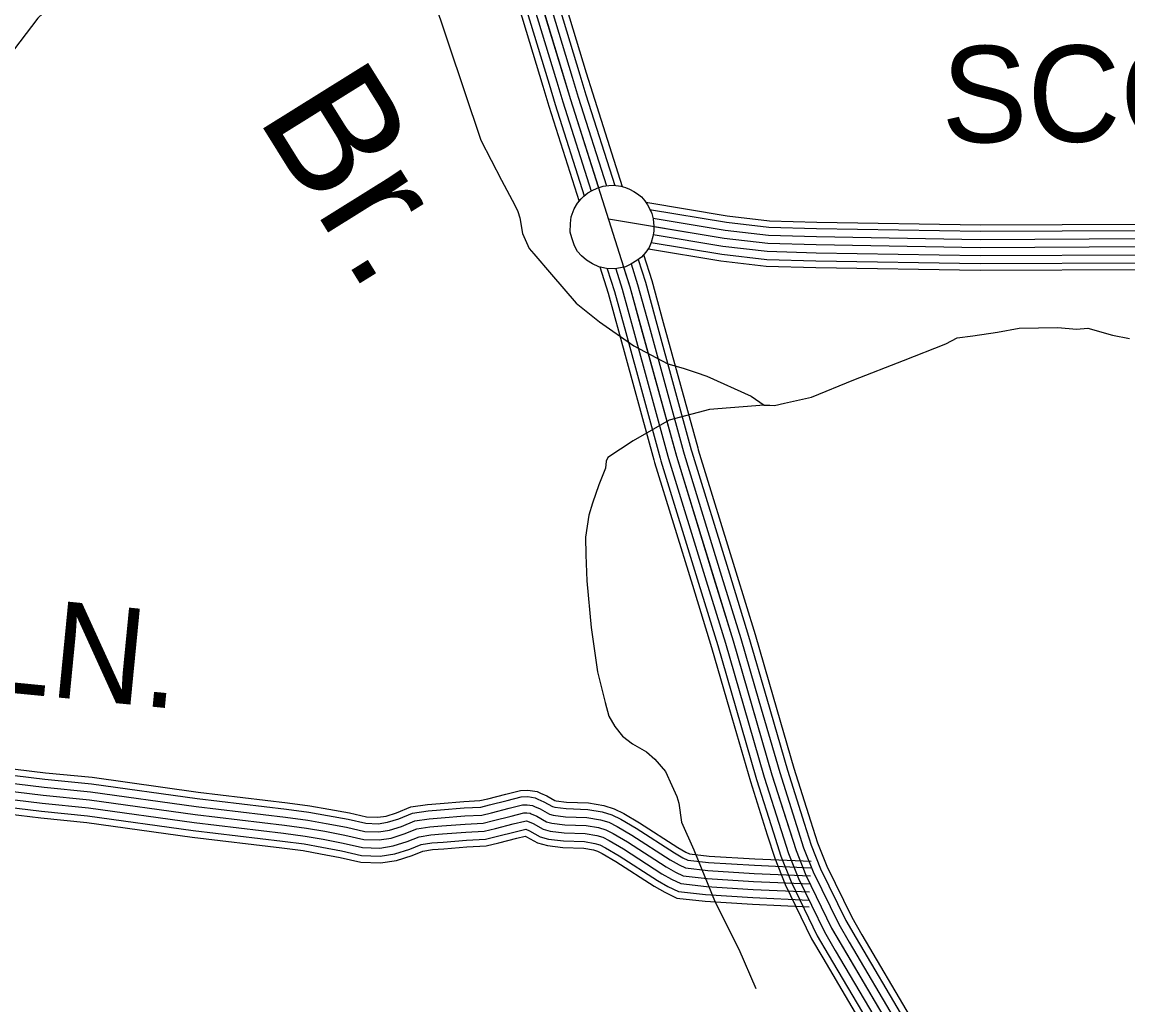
# Model space of a CAD drawing. Extents: x 1551132 to 1791609, y 378168 to 563823.
# Drawn here: x 1653929 to 1658175, y 416489 to 420262 of the extents above; entities that cross this region are included whole.
import ezdxf

# ---------------------------------------------------------------- set-up
doc = ezdxf.new("R2010")
doc.units = 0
for name, color, linetype in [('DESIGN - DRAINAGE - Bridges and Cross Drains Size Text', 7, 'Continuous'), ('DESIGN - ROW - Right-of-Way and Easement Labels', 7, 'Continuous'), ('DESIGN - TRANSPORTATION - Text', 7, 'Continuous'), ('SURVEY - CENTERLINE - Preliminary Text', 7, 'Continuous'), ('SURVEY - CONTOURS - Index with Text', 7, 'Continuous'), ('SURVEY - TRANSPORTATION - Roads', 7, 'Continuous'), ('SURVEY - VEGETATION - Features with Text', 7, 'Continuous')]:
    doc.layers.add(name, color=color, linetype=linetype)

msp = doc.modelspace()

# ---------------------------------------------------------------- linework, layer by layer
at = {"layer": 'DESIGN - TRANSPORTATION - Text'}
for points in [[(1655370.239, 420674.916), (1655323.215, 420654.533), (1655299.141, 420642.682), (1655271, 420620.848), (1655208.709, 420577.222), (1655168.635, 420565.48), (1655134.561, 420553.705), (1655086.529, 420548.038), (1655014.397, 420528.512), (1654904.366, 420523.287), (1654828.36, 420521.82), (1654722.362, 420520.57), (1654632.323, 420515.195), (1654514.267, 420506.02), (1654426.236, 420500.636), (1654370.187, 420493.019), (1654326.047, 420471.294), (1654255.965, 420457.768), (1654215.833, 420438.018), (1654159.659, 420410.375), (1654103.452, 420378.716), (1654051.17, 420335.015), (1653988.788, 420277.364), (1653851.608, 420096.042)], [(1655500.719, 420374.917), (1655690.564, 419808.285), (1655769.562, 419655.473), (1655820.928, 419558.954), (1655832.769, 419534.828), (1655840.611, 419510.736), (1655850.21, 419450.568), (1655875.835, 419392.291), (1655893.701, 419372.132), (1655961.183, 419293.53), (1656056.455, 419182.678), (1656145.987, 419111.926), (1656277.375, 419018.848), (1656408.914, 418949.805), (1656466.804, 418933.363), (1656516.695, 418916.988), (1656558.602, 418902.662), (1656728.09, 418825.335), (1656777.863, 418790.934), (1656799.863, 418790.776), (1656817.862, 418790.651), (1656855.912, 418798.393), (1656960.059, 418821.694), (1657122.489, 418888.654), (1657312.976, 418963.422), (1657475.38, 419026.374), (1657519.529, 419050.1), (1657579.578, 419057.692), (1657673.668, 419071.042), (1657757.766, 419086.476), (1657905.779, 419089.434), (1657977.735, 419082.909), (1658021.751, 419086.609), (1658115.574, 419059.9), (1658181.489, 419047.408)], [(1656777.863, 418790.934), (1656567.927, 418775.317), (1656413.064, 418734.008), (1656275.408, 418654.831), (1656177.952, 418590.929), (1656171.861, 418576.945), (1656169.677, 418548.919), (1656143.253, 418485.001), (1656118.795, 418415.057), (1656104.496, 418369.081), (1656091.946, 418285.037), (1656093.504, 418216.911), (1656096.846, 418116.725), (1656113.678, 417938.32), (1656138.561, 417767.865), (1656167.785, 417649.462), (1656181.443, 417597.286), (1656205.176, 417557.052), (1656234.942, 417520.784), (1656272.741, 417490.467), (1656326.54, 417460.032), (1656358.347, 417431.765), (1656400.046, 417385.389), (1656423.688, 417331.137), (1656443.412, 417288.928), (1656451.245, 417262.827), (1656460.77, 417190.642), (1656508.069, 417084.139), (1656590.75, 416883.226), (1656681.564, 416702.288), (1656746.571, 416551.584)]]:
    msp.add_lwpolyline(points, dxfattribs=at)
at = {"layer": 'SURVEY - CENTERLINE - Preliminary Text'}
for points in [[(1655852.144, 420567.031), (1656034.773, 419964.59), (1656262.767, 419245.613), (1656441.104, 418595.096), (1656659.149, 417886.202), (1656808.27, 417372.164), (1656900.643, 417080.964), (1656938.134, 416986.529), (1657037.056, 416783.482), (1657263.076, 416399.263), (1657481.045, 416009.087), (1657530.436, 415896.542), (1657577.685, 415759.955), (1657642.625, 415569.133), (1657699.398, 415352.311), (1657761.688, 415053.27), (1657882.535, 414501.314), (1658040.423, 413782.77)], [(1655896.06, 420529.03), (1656041.115, 420050.517)], [(1655925.726, 420538.021), (1656070.781, 420059.509)], [(1655950.334, 420545.488), (1656095.388, 420066.976)], [(1655783.413, 420494.879), (1655928.467, 420016.366)], [(1655807.062, 420502.054), (1655952.117, 420023.541)], [(1655836.728, 420511.046), (1655981.783, 420032.533)], [(1655866.394, 420520.038), (1656011.449, 420041.525)], [(1656070.781, 420059.526), (1656093.988, 419982.957), (1656204.577, 419634.223)], [(1656095.388, 420066.984), (1656118.554, 419990.574), (1656232.66, 419630.748)], [(1655928.459, 420016.383), (1655951.95, 419938.906), (1656067.689, 419573.921)], [(1655952.117, 420023.558), (1655975.558, 419946.223), (1656087.022, 419594.713)], [(1655981.783, 420032.55), (1656005.165, 419955.406), (1656113.596, 419613.472)], [(1656011.449, 420041.542), (1656034.773, 419964.59), (1656142.004, 419626.431)], [(1656041.115, 420050.534), (1656064.381, 419973.773), (1656172.27, 419633.548)], [(1656267.409, 419333.515), (1656292.5, 419254.396), (1656336.382, 419094.367)], [(1656294.458, 419350.774), (1656322.233, 419263.188), (1656366.273, 419102.559)], [(1656315.541, 419369.383), (1656346.899, 419270.48), (1656391.073, 419109.359)], [(1656147.337, 419322.748), (1656179.594, 419221.029), (1656222.851, 419063.233)], [(1656175.761, 419314.873), (1656203.302, 419228.037), (1656246.693, 419069.775)], [(1656208.244, 419314.998), (1656233.035, 419236.829), (1656276.584, 419077.967)], [(1656238.776, 419321.265), (1656262.767, 419245.613), (1656306.483, 419086.167)], [(1656276.575, 419077.983), (1656408.772, 418595.762)], [(1656306.475, 419086.184), (1656438.671, 418603.963)], [(1656336.374, 419094.384), (1656468.57, 418612.163)], [(1656366.265, 419102.576), (1656498.461, 418620.355)], [(1656391.064, 419109.376), (1656523.261, 418627.155)], [(1656222.843, 419063.258), (1656355.04, 418581.037)], [(1656246.684, 419069.791), (1656378.881, 418587.57)], [(1656468.57, 418612.171), (1656470.879, 418603.746), (1656615.025, 418135.1)], [(1656498.47, 418620.363), (1656500.645, 418612.405), (1656644.649, 418144.209)], [(1656523.269, 418627.155), (1656525.344, 418619.58), (1656669.232, 418151.776)], [(1656355.04, 418581.07), (1656357.823, 418570.887), (1656502.511, 418100.491)], [(1656378.873, 418587.595), (1656381.564, 418577.787), (1656526.136, 418107.758)], [(1656408.772, 418595.787), (1656411.33, 418586.445), (1656555.76, 418116.867)], [(1656438.671, 418603.979), (1656441.104, 418595.096), (1656585.393, 418125.983)], [(1656644.649, 418144.226), (1656718.556, 417903.953), (1656788.096, 417664.213)], [(1656669.232, 418151.792), (1656743.197, 417911.32), (1656812.795, 417671.38)], [(1656526.136, 418107.775), (1656599.742, 417868.452), (1656669.015, 417629.662)], [(1656555.76, 418116.883), (1656629.45, 417877.327), (1656698.781, 417638.304)], [(1656585.393, 418126), (1656659.149, 417886.202), (1656728.556, 417646.938)], [(1656615.025, 418135.117), (1656688.848, 417895.077), (1656758.33, 417655.571)], [(1656502.511, 418100.508), (1656576.059, 417861.376), (1656645.274, 417622.779)], [(1656698.781, 417638.321), (1656778.604, 417363.155), (1656843.394, 417158.908)], [(1656728.556, 417646.954), (1656808.27, 417372.164), (1656872.944, 417168.283)], [(1656758.33, 417655.588), (1656837.936, 417381.172), (1656902.493, 417177.659)], [(1656788.096, 417664.23), (1656867.602, 417390.181), (1656932.042, 417187.034)], [(1656812.795, 417671.397), (1656892.21, 417397.648), (1656956.55, 417194.809)], [(1656645.274, 417622.795), (1656725.289, 417346.971), (1656790.287, 417142.058)], [(1656669.015, 417629.679), (1656748.938, 417354.147), (1656813.845, 417149.533)], [(1656872.935, 417168.3), (1656900.643, 417080.964), (1656938.134, 416986.529), (1657037.056, 416783.482), (1657078.08, 416713.738)], [(1656902.485, 417177.675), (1656929.859, 417091.381), (1656966.516, 416999.054), (1657064.389, 416798.149), (1657104.796, 416729.455)], [(1656932.034, 417187.051), (1656959.075, 417101.807), (1656994.891, 417011.579), (1657091.73, 416812.824), (1657131.521, 416745.172)], [(1656956.542, 417194.826), (1656983.316, 417110.449), (1657018.44, 417021.971), (1657114.404, 416824.991), (1657153.687, 416758.214)], [(1656790.279, 417142.074), (1656818.92, 417051.814), (1656858.744, 416951.486), (1656960.591, 416742.447), (1657003.34, 416669.77)], [(1656813.837, 417149.55), (1656842.211, 417060.122), (1656881.377, 416961.478), (1656982.382, 416754.139), (1657024.64, 416682.304)], [(1656843.386, 417158.925), (1656871.427, 417070.548), (1656909.751, 416974.003), (1657009.724, 416768.815), (1657051.364, 416698.021)], [(1657131.512, 416745.197), (1657316.866, 416430.106), (1657383.106, 416311.528)], [(1657153.67, 416758.231), (1657339.174, 416442.898), (1657405.556, 416324.07)], [(1657078.072, 416713.755), (1657263.076, 416399.263), (1657328.982, 416281.285)], [(1657104.788, 416729.472), (1657289.967, 416414.689), (1657356.048, 416296.402)], [(1657003.332, 416669.787), (1657187.844, 416356.129), (1657253.284, 416238.993)], [(1657024.631, 416682.312), (1657209.285, 416368.421), (1657274.859, 416251.043)], [(1657051.356, 416698.038), (1657236.185, 416383.838), (1657301.916, 416266.168)]]:
    msp.add_lwpolyline(points, dxfattribs=at)
at = {"layer": 'SURVEY - CONTOURS - Index with Text'}
for points in [[(1653598.962, 417431.064), (1654019.369, 417379.912), (1654198.023, 417362.454), (1654604.405, 417305.152), (1654947.447, 417264.552), (1655033.928, 417253.56), (1655106.352, 417240.559), (1655186.308, 417225.551), (1655251.807, 417210.45), (1655295.072, 417208.934), (1655326.505, 417213.875), (1655367.112, 417226.567), (1655421.569, 417248.893), (1655485.201, 417258.327), (1655533.7, 417262.285), (1655625.04, 417269.71), (1655686.255, 417272.852), (1655717.854, 417280.502), (1655785.952, 417297.995), (1655842.101, 417311.603), (1655871.334, 417313.37), (1655906.1, 417308.02), (1655919.833, 417301.145), (1655943.574, 417290.878), (1655974.998, 417273.119), (1655979.498, 417271.911), (1656019.572, 417266.794), (1656103.537, 417264.094), (1656162.335, 417253.819), (1656202.726, 417241.927), (1656239.95, 417222.935), (1656299.532, 417188.234), (1656446.387, 417093.273), (1656477.353, 417075.739), (1656491.502, 417068.997), (1656566.759, 417060.222), (1656742.505, 417049.455), (1656958.133, 417039.955)], [(1652785.914, 417349.136), (1652920.786, 417384.145), (1652980.91, 417403.713), (1653025.375, 417407.096), (1653070.899, 417405.029), (1653194.797, 417394.062), (1653588.362, 417344.995), (1654009.911, 417293.702), (1654187.748, 417276.326), (1654593.255, 417219.15), (1654936.889, 417178.474), (1655020.795, 417167.816), (1655090.694, 417155.265), (1655168.567, 417140.648), (1655240.44, 417124.081), (1655300.33, 417121.973), (1655346.288, 417129.198), (1655396.553, 417144.915)], [(1653595.945, 417406.53), (1654016.669, 417355.337), (1654195.09, 417337.903), (1654601.23, 417280.643), (1654944.439, 417240.018), (1655030.187, 417229.126), (1655101.893, 417216.25), (1655181.25, 417201.35), (1655248.565, 417185.833), (1655296.572, 417184.141), (1655332.146, 417189.742), (1655375.504, 417203.292), (1655428.169, 417224.884), (1655488.018, 417233.751), (1655535.708, 417237.643), (1655626.673, 417245.051), (1655689.821, 417248.285), (1655723.837, 417256.518), (1655791.936, 417274.019), (1655845.784, 417287.069), (1655870.184, 417288.536), (1655898.5, 417284.186), (1655909.383, 417278.736), (1655932.557, 417268.711), (1655965.573, 417250.052), (1655974.715, 417247.61), (1656017.605, 417242.127), (1656101.003, 417239.443), (1656156.694, 417229.71), (1656193.543, 417218.868), (1656228.109, 417201.226), (1656286.599, 417167.166), (1656433.57, 417072.122), (1656465.928, 417053.805), (1656484.569, 417044.922), (1656564.576, 417035.596), (1656741.205, 417024.771), (1656957.042, 417015.263)], [(1653588.362, 417344.995), (1654009.911, 417293.702), (1654187.748, 417276.326), (1654593.255, 417219.15), (1654936.889, 417178.474), (1655020.795, 417167.816), (1655090.694, 417155.265), (1655168.567, 417140.648), (1655240.44, 417124.081), (1655300.33, 417121.973), (1655346.288, 417129.198), (1655396.553, 417144.915), (1655444.71, 417164.658), (1655495.093, 417172.124), (1655540.741, 417175.85), (1655630.773, 417183.175), (1655698.779, 417186.658), (1655738.845, 417196.359), (1655806.952, 417213.859), (1655855.026, 417225.509), (1655867.309, 417226.251), (1655879.442, 417224.384), (1655883.167, 417222.518), (1655904.925, 417213.109), (1655941.94, 417192.192), (1655962.723, 417186.633), (1656012.672, 417180.25), (1656094.637, 417177.617), (1656142.561, 417169.241), (1656170.502, 417161.016), (1656198.393, 417146.783), (1656254.15, 417114.315), (1656401.438, 417019.071), (1656437.287, 416998.77), (1656467.178, 416984.528), (1656559.084, 416973.811), (1656737.947, 416962.853), (1656954.317, 416953.319)], [(1653592.154, 417375.762), (1654013.294, 417324.519), (1654191.423, 417307.119), (1654597.239, 417249.893), (1654940.664, 417209.242), (1655025.487, 417198.467), (1655096.294, 417185.758), (1655174.908, 417170.999), (1655244.507, 417154.957), (1655298.455, 417153.057), (1655339.213, 417159.466), (1655386.028, 417174.108), (1655436.436, 417194.775), (1655491.559, 417202.942), (1655538.225, 417206.75), (1655628.723, 417214.109), (1655694.305, 417217.467), (1655731.337, 417226.434), (1655799.444, 417243.935), (1655850.401, 417256.285), (1655868.75, 417257.394), (1655888.975, 417254.285), (1655896.275, 417250.627), (1655918.741, 417240.91), (1655953.757, 417221.118), (1655968.723, 417217.118), (1656015.139, 417211.184), (1656097.82, 417208.534), (1656149.627, 417199.476), (1656182.026, 417189.942), (1656213.251, 417174.008), (1656270.374, 417140.741), (1656417.504, 417045.597), (1656451.612, 417026.288), (1656475.869, 417014.729), (1656561.826, 417004.704), (1656739.58, 416993.812), (1656955.683, 416984.287)], [(1653584.571, 417314.227), (1654006.527, 417262.884), (1654184.073, 417245.534), (1654589.272, 417188.408), (1654933.114, 417147.707), (1655016.104, 417137.165), (1655085.094, 417124.773), (1655162.225, 417110.298), (1655236.374, 417093.206), (1655302.205, 417090.889), (1655353.362, 417098.931), (1655407.078, 417115.723), (1655452.985, 417134.54), (1655498.626, 417141.307), (1655543.258, 417144.949), (1655632.823, 417152.241), (1655703.254, 417155.849), (1655746.353, 417166.283), (1655814.46, 417183.783), (1655859.651, 417194.734), (1655865.867, 417195.109), (1655869.909, 417194.484), (1655870.059, 417194.409), (1655891.108, 417185.308), (1655930.124, 417163.266), (1655956.723, 417156.149), (1656010.205, 417149.316), (1656091.454, 417146.699), (1656135.494, 417139.007), (1656158.977, 417132.09), (1656183.535, 417119.557), (1656237.925, 417087.889), (1656385.372, 416992.545), (1656422.962, 416971.253), (1656458.487, 416954.328), (1656556.343, 416942.919), (1656736.313, 416931.894), (1656952.95, 416922.352)], [(1653577.637, 417257.934), (1654000.344, 417206.5), (1654177.357, 417189.208), (1654581.972, 417132.156), (1654926.206, 417091.405), (1655007.512, 417081.08), (1655074.852, 417068.988), (1655150.617, 417054.763), (1655228.94, 417036.712), (1655305.647, 417034.012), (1655366.295, 417043.546), (1655426.327, 417062.322), (1655468.118, 417079.447), (1655505.101, 417084.931), (1655547.866, 417088.422), (1655636.573, 417095.639), (1655711.454, 417099.473), (1655760.078, 417111.248), (1655828.193, 417128.748), (1655860.759, 417136.64), (1655865.834, 417134.449), (1655908.499, 417110.331), (1655945.757, 417100.373), (1656005.689, 417092.706), (1656085.637, 417090.139), (1656122.561, 417083.689), (1656137.902, 417079.172), (1656156.36, 417069.755), (1656208.242, 417039.538), (1656355.972, 416944.011), (1656396.763, 416920.91), (1656442.579, 416899.084), (1656551.318, 416886.401), (1656733.33, 416875.251), (1656950.458, 416865.684)], [(1653580.779, 417283.46), (1654003.152, 417232.067), (1654180.407, 417214.75), (1654585.28, 417157.657), (1654929.339, 417116.931), (1655011.404, 417106.506), (1655079.494, 417094.281), (1655155.884, 417079.947), (1655232.315, 417062.33), (1655304.089, 417059.805), (1655360.429, 417068.655), (1655417.603, 417086.539), (1655461.252, 417104.431), (1655502.167, 417110.498), (1655545.775, 417114.056), (1655634.873, 417121.298), (1655707.738, 417125.032), (1655753.853, 417136.199), (1655821.968, 417153.699), (1655863.067, 417163.658), (1655877.292, 417157.508), (1655918.308, 417134.332), (1655950.732, 417125.657), (1656007.739, 417118.373), (1656088.27, 417115.79), (1656128.428, 417108.773), (1656147.461, 417103.165), (1656168.677, 417092.339), (1656221.7, 417061.464), (1656369.305, 416966.02), (1656408.646, 416943.736), (1656449.787, 416924.135), (1656553.593, 416912.027), (1656734.688, 416900.935), (1656951.592, 416891.376)], [(1655396.553, 417144.915), (1655444.71, 417164.658), (1655495.093, 417172.124), (1655540.741, 417175.85), (1655630.773, 417183.175), (1655698.779, 417186.658), (1655738.845, 417196.359), (1655806.952, 417213.859), (1655855.026, 417225.509), (1655867.309, 417226.251), (1655879.442, 417224.384), (1655883.167, 417222.518), (1655904.925, 417213.109), (1655941.94, 417192.192), (1655962.723, 417186.633), (1656012.672, 417180.25), (1656094.637, 417177.617), (1656142.561, 417169.241), (1656170.502, 417161.016), (1656198.393, 417146.783), (1656254.15, 417114.315), (1656401.438, 417019.071), (1656437.287, 416998.77), (1656467.178, 416984.528), (1656559.084, 416973.811), (1656737.947, 416962.853), (1656954.317, 416953.319)]]:
    msp.add_lwpolyline(points, dxfattribs=at)
at = {"layer": 'SURVEY - TRANSPORTATION - Roads'}
for points in [[(1656323.349, 419570.58), (1656636.625, 419518.312), (1656798.588, 419499.678), (1656980.284, 419494.361), (1657608.586, 419483.561), (1658236.213, 419486.762), (1658798.425, 419480.454), (1659284.147, 419478.737), (1659536.857, 419476.804), (1659557.757, 419479.254), (1659578.348, 419484.512), (1659675.463, 419541.514), (1659737.028, 419570.756), (1659841.509, 419611.474), (1659986.847, 419658.075), (1660114.977, 419690.685), (1660180.026, 419701.81), (1660269.94, 419705.31), (1660365.621, 419712.91), (1660534.759, 419705.26), (1660717.113, 419680.751), (1660829.794, 419652.667), (1660992.907, 419611.016), (1661362.59, 419505.356)], [(1656337.649, 419543.137), (1656633.175, 419493.828), (1656796.813, 419475.002), (1656979.717, 419469.652), (1657608.436, 419458.844), (1658236.138, 419462.044), (1658798.241, 419455.736), (1659284.013, 419454.02), (1659538.207, 419452.07), (1659562.273, 419454.895), (1659587.848, 419461.428), (1659687.037, 419519.647), (1659746.828, 419548.047), (1659849.775, 419588.165), (1659993.68, 419634.308), (1660120.111, 419666.492), (1660182.601, 419677.168), (1660271.407, 419680.635), (1660366.038, 419688.143), (1660532.551, 419680.618), (1660712.463, 419656.434), (1660823.752, 419628.7), (1660986.449, 419587.157), (1661355.415, 419481.697)], [(1656351.615, 419509.37), (1656628.851, 419463.119), (1656794.58, 419444.052), (1656978.992, 419438.66), (1657608.244, 419427.843), (1658236.038, 419431.044), (1658798.008, 419424.735), (1659283.838, 419423.019), (1659539.907, 419421.061), (1659567.948, 419424.352), (1659599.764, 419432.478), (1659701.562, 419492.229), (1659759.127, 419519.572), (1659860.15, 419558.939), (1660002.238, 419604.499), (1660126.56, 419636.142), (1660185.834, 419646.275), (1660273.232, 419649.675), (1660366.571, 419657.092), (1660529.776, 419649.709), (1660706.638, 419625.933), (1660816.169, 419598.641), (1660978.349, 419557.223), (1661346.432, 419452.029)], [(1656180.011, 419506.578), (1656624.526, 419432.409), (1656792.355, 419413.101), (1656978.276, 419407.667), (1657608.061, 419396.842), (1658235.946, 419400.043), (1658797.783, 419393.735), (1659283.663, 419392.018), (1659541.599, 419390.043), (1659573.615, 419393.802), (1659611.681, 419403.527), (1659716.087, 419464.804), (1659771.419, 419491.088), (1659870.516, 419529.705), (1660010.805, 419574.69), (1660133.002, 419605.791), (1660189.059, 419615.374), (1660275.065, 419618.725), (1660367.096, 419626.033), (1660527.009, 419618.8), (1660700.805, 419595.441), (1660808.586, 419568.582), (1660970.257, 419527.298), (1661337.44, 419422.353)], [(1656352.099, 419446.435), (1656620.201, 419401.7), (1656790.13, 419382.15), (1656977.559, 419376.675), (1657607.878, 419365.842), (1658235.855, 419369.042), (1658797.558, 419362.734), (1659283.488, 419361.017), (1659543.291, 419359.026), (1659579.281, 419363.251), (1659623.597, 419374.576), (1659730.611, 419437.378), (1659783.71, 419462.604), (1659880.883, 419500.471), (1660019.371, 419544.881), (1660139.443, 419575.44), (1660192.284, 419584.474), (1660276.898, 419587.774), (1660367.621, 419594.974), (1660524.243, 419587.891), (1660694.972, 419564.948), (1660801.003, 419538.523), (1660962.166, 419497.372), (1661328.449, 419392.678)], [(1656354.607, 419477.444), (1656624.526, 419432.409), (1656792.355, 419413.101), (1656978.276, 419407.667), (1657608.061, 419396.842), (1658235.946, 419400.043), (1658797.783, 419393.735), (1659283.663, 419392.018), (1659541.599, 419390.043), (1659573.615, 419393.802), (1659611.681, 419403.527), (1659716.087, 419464.804), (1659771.419, 419491.088), (1659870.516, 419529.705), (1660010.805, 419574.69), (1660133.002, 419605.791), (1660189.059, 419615.374), (1660275.065, 419618.725), (1660367.096, 419626.033), (1660527.009, 419618.8), (1660700.805, 419595.441), (1660808.586, 419568.582), (1660970.257, 419527.298), (1661337.44, 419422.353)], [(1656343.907, 419416.367), (1656615.876, 419370.991), (1656787.897, 419351.199), (1656976.834, 419345.682), (1657607.686, 419334.841), (1658235.755, 419338.041), (1658797.325, 419331.733), (1659283.313, 419330.017), (1659544.991, 419328.017), (1659584.956, 419332.708), (1659635.513, 419345.625), (1659745.136, 419409.961), (1659796.01, 419434.128), (1659891.257, 419471.246), (1660027.929, 419515.072), (1660145.893, 419545.089), (1660195.517, 419553.581), (1660278.723, 419556.815), (1660368.155, 419563.923), (1660521.468, 419556.981), (1660689.147, 419534.448), (1660793.42, 419508.464), (1660954.066, 419467.438), (1661319.466, 419363.01)], [(1656333.949, 419391.967), (1656612.284, 419345.524), (1656786.047, 419325.532), (1656976.242, 419319.973), (1657607.528, 419309.123), (1658235.679, 419312.324), (1658797.133, 419306.016), (1659283.172, 419304.299), (1659546.399, 419302.283), (1659589.656, 419307.366), (1659645.396, 419321.6), (1659757.177, 419387.21), (1659806.201, 419410.502), (1659899.857, 419446.995), (1660035.037, 419490.338), (1660151.235, 419519.914), (1660198.192, 419527.947), (1660280.248, 419531.139), (1660368.596, 419538.156), (1660519.168, 419531.347), (1660684.306, 419509.147), (1660787.128, 419483.53), (1660947.349, 419442.612), (1661312.007, 419338.393)]]:
    msp.add_lwpolyline(points, dxfattribs=at)
at = {"layer": 'SURVEY - VEGETATION - Features with Text'}
msp.add_lwpolyline([(1656074.98, 419583.738), (1656086.43, 419593.988), (1656101.121, 419606.289), (1656117.838, 419615.831), (1656136.462, 419624.648), (1656160.062, 419632.364), (1656182.428, 419635.015), (1656200.377, 419635.715), (1656227.335, 419632.481), (1656245.868, 419627.214), (1656260.651, 419620.798), (1656277.95, 419611.914), (1656291.992, 419602.88), (1656306.758, 419590.83), (1656320.158, 419576.096), (1656330.358, 419560.554), (1656338.666, 419543.971), (1656347.024, 419527.345), (1656352.19, 419506.253), (1656354.757, 419478.819), (1656354.082, 419459.643), (1656350.915, 419438.359), (1656343.799, 419415.934), (1656336.857, 419396.233), (1656323.458, 419378.208), (1656307.375, 419360.149), (1656288.883, 419346.215), (1656266.376, 419332.082), (1656245.893, 419323.023), (1656226.127, 419317.99), (1656204.844, 419314.814), (1656172.269, 419316.173), (1656143.978, 419323.098), (1656119.179, 419334.007), (1656095.938, 419348.115), (1656076.797, 419364.807), (1656062.064, 419381.483), (1656049.981, 419402.508), (1656039.698, 419433.292), (1656033.856, 419454.976), (1656034.623, 419488.286), (1656037.123, 419514.611), (1656048.672, 419545.337), (1656060.897, 419566.396)], close=True, dxfattribs=at)

# ---------------------------------------------------------------- texts
at = {"layer": 'DESIGN - DRAINAGE - Bridges and Cross Drains Size Text'}
msp.add_text('Br.', height=475.0056, rotation=301.940658, dxfattribs=at).set_placement((1654826.965, 419898.542))
at = {"layer": 'DESIGN - ROW - Right-of-Way and Easement Labels'}
for s, height, rotation, p in [('SCOTT', 369.9913, 0.292161, (1657459.906, 419799.811)), ('LN.', 369.9915, 354.419283, (1653755.659, 417699.362))]:
    msp.add_text(s, height=height, rotation=rotation, dxfattribs=at).set_placement(p)

doc.saveas('drawing.dxf')
